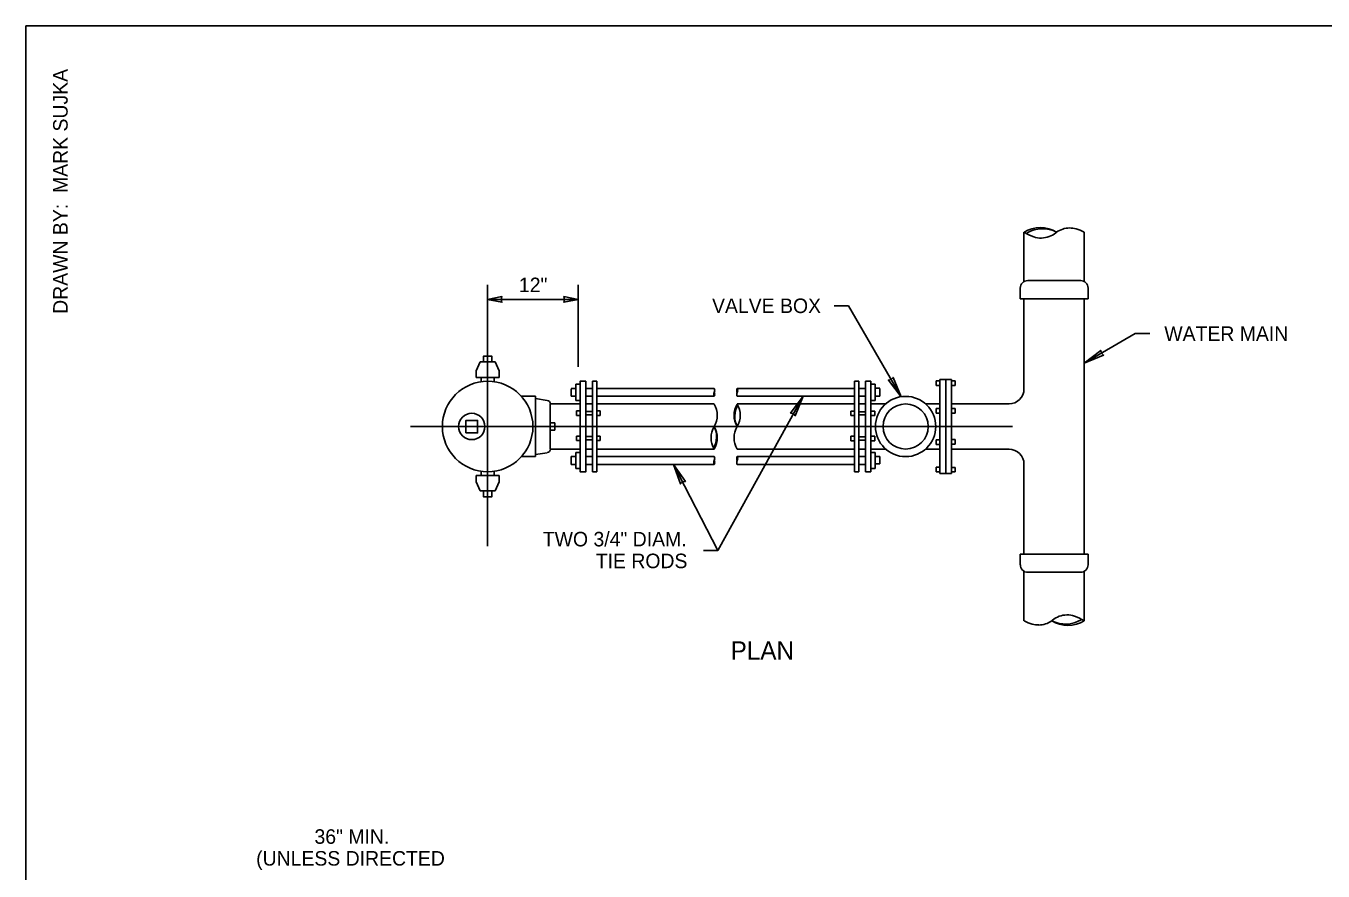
# Model space of a CAD drawing. Extents: x 99862 to 103151, y 100000 to 102076.
# Drawn here: x 99862 to 101292, y 101144 to 102076 of the extents above; entities that cross this region are included whole.
import ezdxf

# ---------------------------------------------------------------- set-up
doc = ezdxf.new("R2010")
doc.units = 0
for name, color, linetype in [('Level 1', 7, 'Continuous'), ('Level 15', 7, 'Continuous'), ('Level 18', 7, 'Continuous'), ('Level 20', 7, 'Continuous'), ('Level 6', 7, 'Continuous'), ('Level 62', 7, 'Continuous')]:
    doc.layers.add(name, color=color, linetype=linetype)

msp = doc.modelspace()

# ---------------------------------------------------------------- linework, layer by layer
at = {"layer": 'Level 1'}
msp.add_lwpolyline([(99862, 99999.5), (103151, 99999.5), (103151, 102075.5), (99862, 102075.5)], close=True, dxfattribs=at)
at = {"layer": 'Level 15'}
for p, q in [((100371, 101790.2), (100371, 101502.4)), ((100470.8, 101790.2), (100470.8, 101700.1)), ((100470.8, 101774.2), (100371, 101774.2)), ((100753, 101767.2), (100769, 101767.2)), ((100826.8, 101667), (100769, 101767.2)), ((101028.7, 101704), (101085, 101736.5)), ((101085, 101736.5), (101101, 101736.5)), ((100718.7, 101667.5), (100624.9, 101497.6)), ((100285.8, 101634.3), (100949.7, 101634.3)), ((100575.9, 101592.5), (100624.9, 101497.6)), ((100608.9, 101497.6), (100624.9, 101497.6))]:
    msp.add_line(p, q, dxfattribs=at)
for points in [[(100371, 101774.2), (100386.7, 101771.1), (100386, 101774.2), (100386.7, 101777.3)], [(100470.8, 101774.2), (100455, 101771.1), (100455.8, 101774.2), (100455, 101777.3)], [(101028.7, 101704), (101047, 101718), (101047.6, 101714.9), (101050, 101712.9)], [(100826.8, 101667), (100818, 101688.3), (100815.9, 101685.9), (100812.8, 101685.3)], [(100718.7, 101667.5), (100710.2, 101646.1), (100708.1, 101648.4), (100705, 101648.9)], [(100575.9, 101592.5), (100589, 101573.6), (100585.9, 101573.2), (100583.7, 101570.9)]]:
    msp.add_lwpolyline(points, close=True, dxfattribs=at)
at = {"layer": 'Level 18'}
for p, q in [((100358.2, 101695.5), (100362.8, 101705.3)), ((100379.3, 101705.3), (100362.8, 101705.3)), ((100383.8, 101695.5), (100379.3, 101705.3)), ((100358.2, 101688.3), (100358.2, 101695.5)), ((100383.8, 101688.3), (100358.2, 101688.3)), ((100363.8, 101683.5), (100363.8, 101688.3)), ((100378.2, 101683.5), (100378.2, 101688.3)), ((100383.8, 101688.3), (100383.8, 101695.5)), ((100463.2, 101676), (100468.2, 101676)), ((100463.2, 101675.7), (100463.2, 101667.5)), ((100468.2, 101680.9), (100468.2, 101663)), ((100468.2, 101680.9), (100472.9, 101680.9)), ((100479.3, 101676), (100486.7, 101676)), ((100491.2, 101676), (100620.8, 101676)), ((100646.1, 101676), (100775.5, 101676)), ((100775.5, 101684), (100780.1, 101684)), ((100775.5, 101584.3), (100775.5, 101684)), ((100780.1, 101684), (100780.1, 101584.3)), ((100787.5, 101676), (100780.1, 101676)), ((100787.5, 101684), (100793.6, 101684)), ((100787.5, 101584.3), (100787.5, 101684)), ((100793.6, 101684), (100793.6, 101584.3)), ((100798.4, 101680.9), (100793.8, 101680.9)), ((100798.4, 101663), (100798.4, 101680.9)), ((100803.5, 101676.5), (100798.4, 101676.5)), ((100803.5, 101667.7), (100803.5, 101676.2)), ((100869.7, 101684.4), (100865.4, 101684.4)), ((100865.4, 101679.4), (100865.4, 101684.4)), ((100869.7, 101679.4), (100865.4, 101679.4)), ((100869.7, 101582.4), (100869.7, 101686.1)), ((100869.7, 101686.1), (100882.2, 101686.1)), ((100876.3, 101582.4), (100876.3, 101686.1)), ((100882.2, 101582.4), (100882.2, 101686.1)), ((100882.2, 101684.4), (100886.3, 101684.4)), ((100882.2, 101679.4), (100886.3, 101679.4)), ((100886.3, 101679.4), (100886.3, 101684.4)), ((100408.2, 101667.5), (100423.7, 101667.5)), ((100423.7, 101667.5), (100423.7, 101601)), ((100423.7, 101664.9), (100436.7, 101663)), ((100463.2, 101667.5), (100468.2, 101667.5)), ((100468.2, 101663), (100472.9, 101663)), ((100479.3, 101667.5), (100486.7, 101667.5)), ((100491.2, 101667.5), (100620.8, 101667.5)), ((100646.1, 101667.5), (100775.5, 101667.5)), ((100787.5, 101667.5), (100780.1, 101667.5)), ((100798.4, 101663), (100793.8, 101663)), ((100803.5, 101667.7), (100798.4, 101667.7)), ((100440.1, 101659), (100472.9, 101659)), ((100440.1, 101659), (100440.1, 101609.5)), ((100472.9, 101651.4), (100468.8, 101651.4)), ((100468.8, 101646.4), (100468.8, 101651.4)), ((100468.8, 101646.4), (100472.9, 101646.4)), ((100479.3, 101650.7), (100486.7, 101650.7)), ((100486.7, 101647.2), (100479.3, 101647.2)), ((100491.2, 101651.4), (100495.2, 101651.4)), ((100495.2, 101646.4), (100491.2, 101646.4)), ((100495.2, 101646.4), (100495.2, 101651.4)), ((100775.5, 101651.2), (100771.4, 101651.2)), ((100771.4, 101646.2), (100771.4, 101651.2)), ((100771.4, 101646.2), (100775.5, 101646.2)), ((100780, 101646.9), (100787.5, 101646.9)), ((100787.5, 101650.5), (100780.1, 101650.5)), ((100793.6, 101651.2), (100797.9, 101651.2)), ((100797.9, 101646.2), (100793.6, 101646.2)), ((100797.9, 101646.2), (100797.9, 101651.2)), ((100865.5, 101648.9), (100865.5, 101653.9)), ((100869.7, 101653.9), (100865.5, 101653.9)), ((100869.6, 101648.9), (100865.5, 101648.9)), ((100882.2, 101653.9), (100886.3, 101653.9)), ((100882.2, 101648.9), (100886.3, 101648.9)), ((100886.3, 101648.9), (100886.3, 101653.9)), ((100445, 101638.3), (100440.1, 101638.3)), ((100445, 101638.3), (100445, 101630)), ((100445, 101630), (100440.1, 101630)), ((100468.8, 101623.7), (100472.9, 101623.7)), ((100468.8, 101618.7), (100468.8, 101623.7)), ((100468.8, 101618.7), (100472.9, 101618.7)), ((100486.7, 101623), (100479.3, 101623)), ((100486.7, 101619.5), (100479.3, 101619.5)), ((100495.2, 101623.7), (100491.2, 101623.7)), ((100495.2, 101618.7), (100491.2, 101618.7)), ((100495.2, 101618.7), (100495.2, 101623.7)), ((100771.4, 101623.5), (100775.5, 101623.5)), ((100771.4, 101618.5), (100771.4, 101623.5)), ((100771.4, 101618.5), (100775.5, 101618.5)), ((100780.1, 101622.8), (100787.5, 101622.8)), ((100780.1, 101619.3), (100787.5, 101619.3)), ((100797.8, 101623.5), (100793.6, 101623.5)), ((100797.8, 101618.5), (100793.6, 101618.5)), ((100797.8, 101618.5), (100797.8, 101623.5)), ((100865.4, 101614.5), (100865.4, 101619.5)), ((100869.7, 101619.5), (100865.4, 101619.5)), ((100882.2, 101619.8), (100886.4, 101619.8)), ((100886.4, 101614.9), (100886.4, 101619.8)), ((100423.7, 101603.4), (100436.7, 101605.3)), ((100440.1, 101609.3), (100472.9, 101609.3)), ((100468.2, 101605.7), (100468.2, 101587.9)), ((100468.2, 101605.7), (100472.9, 101605.7)), ((100798.4, 101605.7), (100793.8, 101605.7)), ((100798.4, 101587.9), (100798.4, 101605.7)), ((100869.7, 101614.5), (100865.4, 101614.5)), ((100882.2, 101614.9), (100886.4, 101614.9)), ((100408.2, 101601), (100423.7, 101601)), ((100463.2, 101601), (100468.2, 101601)), ((100463.2, 101601), (100463.2, 101592.5)), ((100463.2, 101592.5), (100468.2, 101592.5)), ((100468.2, 101587.9), (100472.9, 101587.9)), ((100479.3, 101601), (100486.7, 101601)), ((100479.3, 101592.5), (100486.7, 101592.5)), ((100491.2, 101601), (100620.8, 101601)), ((100491.2, 101592.5), (100620.8, 101592.5)), ((100646.1, 101601), (100775.5, 101601)), ((100646.1, 101592.5), (100775.5, 101592.5)), ((100787.5, 101601), (100780.1, 101601)), ((100787.5, 101592.5), (100780.1, 101592.5)), ((100798.4, 101587.9), (100793.8, 101587.9)), ((100803.5, 101601.2), (100798.4, 101601.2)), ((100803.5, 101593), (100798.4, 101593)), ((100803.5, 101593), (100803.5, 101601.2)), ((100865.3, 101584.3), (100865.3, 101589.3)), ((100869.7, 101589.3), (100865.3, 101589.3)), ((100882.2, 101589.2), (100886.3, 101589.2)), ((100886.3, 101584.3), (100886.3, 101589.2)), ((100358.2, 101580.2), (100358.2, 101573.1)), ((100383.8, 101580.2), (100358.2, 101580.2)), ((100363.8, 101584.8), (100363.8, 101580.6)), ((100378.2, 101584.8), (100378.2, 101580.6)), ((100383.8, 101580.2), (100383.8, 101573.1)), ((100780.1, 101584.3), (100775.5, 101584.3)), ((100793.6, 101584.3), (100787.5, 101584.3)), ((100869.7, 101584.3), (100865.3, 101584.3)), ((100882.2, 101582.4), (100869.7, 101582.4)), ((100882.2, 101584.3), (100886.3, 101584.3)), ((100358.2, 101573.1), (100362.8, 101563.2)), ((100379.3, 101563.2), (100362.8, 101563.2)), ((100383.8, 101573.1), (100379.3, 101563.2))]:
    msp.add_line(p, q, dxfattribs=at)
for points in [[(100366.5, 101705.3), (100366.5, 101711.7), (100375.5, 101711.7), (100375.5, 101705.3)], [(100479.3, 101684), (100472.9, 101684), (100472.9, 101584.3), (100479.3, 101584.3)], [(100491.2, 101684), (100486.7, 101684), (100486.7, 101584.3), (100491.2, 101584.3)], [(100347.1, 101627.1), (100347.1, 101640.9), (100359.9, 101640.9), (100359.9, 101627.1)], [(100366.5, 101563.2), (100366.5, 101556.6), (100375.5, 101556.6), (100375.5, 101563.2)]]:
    msp.add_lwpolyline(points, close=True, dxfattribs=at)
for centre, radius in [((100371, 101634.2), 49.9), ((100353.5, 101634.2), 14.5)]:
    msp.add_circle(centre, radius, dxfattribs=at)
for centre, radius, start, end in [((100617.1, 101673.9), 4.26, 330, 30), ((100649.8, 101673.9), 4.26, 150, 210), ((100642.4, 101673.9), 4.26, 330, 30), ((100436.1, 101658.9), 4.16, 0, 81.5048), ((100624.5, 101669.6), 4.26, 150, 210), ((100617.1, 101669.6), 4.26, 330, 30), ((100649.8, 101669.6), 4.26, 150, 210), ((100436.1, 101609.5), 4.16, 278.4952, 0), ((100624.5, 101594.6), 4.26, 150, 210), ((100617.1, 101598.9), 4.26, 330, 30), ((100617.1, 101594.6), 4.26, 330, 30), ((100649.8, 101598.9), 4.26, 150, 210), ((100649.8, 101594.6), 4.26, 150, 210), ((100642.4, 101598.9), 4.26, 330, 30)]:
    msp.add_arc(centre, radius, start, end, dxfattribs=at)
at = {"layer": 'Level 6'}
for p, q in [((100962.3, 101793.8), (100962.3, 101848.3)), ((101028.7, 101793.8), (101028.7, 101848.3)), ((100966.5, 101794.9), (101024.8, 101794.9)), ((100958.2, 101774.9), (100958.2, 101786.6)), ((100958.2, 101774.9), (101033, 101774.9)), ((100962.3, 101774.9), (100962.3, 101675.7)), ((101028.7, 101774.9), (101028.7, 101493.6)), ((101033, 101774.9), (101033, 101786.6)), ((100479.3, 101659), (100486.7, 101659)), ((100491.2, 101659), (100620.8, 101659)), ((100646.1, 101659), (100775.5, 101659)), ((100780.1, 101659), (100787.5, 101659)), ((100793.6, 101659), (100809.9, 101659)), ((100853.7, 101659), (100869.7, 101659)), ((100882.2, 101659), (100945.8, 101659)), ((100479.3, 101609.3), (100486.7, 101609.3)), ((100491.2, 101609.3), (100620.8, 101609.3)), ((100646.1, 101609.3), (100775.5, 101609.3)), ((100780.1, 101609.3), (100787.5, 101609.3)), ((100793.6, 101609.3), (100809.9, 101609.3)), ((100853.7, 101609.3), (100869.7, 101609.3)), ((100882.2, 101609.3), (100945.8, 101609.3)), ((100962.3, 101592.5), (100962.3, 101493.6)), ((100958.2, 101493.6), (101033, 101493.6)), ((100958.2, 101493.6), (100958.2, 101481.9)), ((101033, 101493.6), (101033, 101481.9)), ((100962.3, 101474.8), (100962.3, 101420.2)), ((100966.6, 101473.6), (101024.7, 101473.6)), ((101028.7, 101474.6), (101028.7, 101420.2))]:
    msp.add_line(p, q, dxfattribs=at)
for radius in [33.2, 24.9]:
    msp.add_circle((100831.8, 101634.2), radius, dxfattribs=at)
for centre, radius, start, end in [((100980.3, 101819), 34.3, 58.4529, 121.498), ((100987.9, 101887.4), 46.7, 236.8182, 251.4001), ((100966, 101846.8), 0.601, 116.2867, 233.1869), ((100982.8, 101817.8), 34.2, 63.1557, 120.0502), ((100981.1, 101867.5), 25.7, 271.2806, 308.8913), ((101012.6, 101828.3), 24.6, 125.844, 128.8913), ((101012.6, 101828.3), 24.6, 90.4152, 125.844), ((101012.6, 101826.9), 26, 74.2217, 90.4152), ((101006.9, 101806.8), 46.9, 62.1809, 74.2217), ((100981.1, 101867), 25.3, 251.4001, 271.2806), ((100966.5, 101786.6), 8.31, 90, 180), ((101024.7, 101786.6), 8.31, 0, 90), ((100945.7, 101675.7), 16.6, 270, 0), ((100599.3, 101646.5), 24.9, 330, 30), ((100667.6, 101646.5), 24.9, 150, 210), ((100668.5, 101645.2), 25, 150.1832, 206.3935), ((100624.6, 101646.5), 24.9, 330, 30), ((100642.3, 101621.7), 24.9, 150, 210), ((100598.4, 101623), 25, 330.1832, 26.3935), ((100599.3, 101621.7), 24.9, 330, 30), ((100667.6, 101621.7), 24.9, 150, 210), ((100945.7, 101592.6), 16.6, 0, 90), ((100966.6, 101481.9), 8.31, 180, 270), ((101024.7, 101481.9), 8.31, 270, 0), ((100984.2, 101461.6), 46.9, 242.1809, 254.2217), ((100978.5, 101441.5), 26, 254.2217, 270.4152), ((100978.5, 101440), 24.6, 270.4152, 305.844), ((101008.2, 101450.5), 34, 243.2702, 300.1646), ((100978.5, 101440), 24.6, 305.844, 308.8913), ((101010.8, 101449.4), 34.3, 238.4529, 301.498), ((101010, 101400.9), 25.7, 91.2806, 128.8913), ((101010, 101401.3), 25.3, 71.4001, 91.2806), ((101003.2, 101381), 46.7, 56.8182, 71.4001), ((101025, 101421.6), 0.601, 296.2867, 53.1869), ((101010.8, 101449.4), 34.3, 301.4980217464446, 301.4980222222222)]:
    msp.add_arc(centre, radius, start, end, dxfattribs=at)

# ---------------------------------------------------------------- texts
at = {"layer": 'Level 20'}
for s, height, p in [('12"', 16, (100405.5, 101782.2)), ('VALVE BOX', 16, (100618.4, 101759.2)), ('WATER MAIN', 16, (101117, 101728.5)), ('TWO 3/4" DIAM.', 16, (100431.8, 101502.1)), ('TIE RODS', 16, (100490.2, 101478.1)), ('PLAN', 20, (100638.9, 101377.4)), ('36" MIN.', 16, (100180.1, 101174.4)), ('(UNLESS DIRECTED', 16, (100115.8, 101150.4))]:
    msp.add_text(s, height=height, dxfattribs=at).set_placement(p)
at = {"layer": 'Level 62'}
msp.add_text('DRAWN BY:  MARK SUJKA', height=16, rotation=90, dxfattribs=at).set_placement((99908, 101758.3))

doc.saveas('drawing.dxf')
